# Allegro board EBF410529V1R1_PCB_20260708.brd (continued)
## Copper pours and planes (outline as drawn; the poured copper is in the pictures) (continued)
VCCA1V8_PLDO2_S0 on ART03: 19.24,54.5 19.46,54.71 32.26,54.71 36.53,58.98 36.53,62.76 36.75,62.99 41.5,62.99 41.73,62.76 41.73,61.85 41.48,61.59 38.86,61.59 38.43,61.16 38.43,58.37 33.76,53.7 19.46,53.7 19.24,53.91
VDD_3V3 on TOP: 57.86,13.82 57.86,12.67 57.96,12.57 59.18,12.57 59.69,13.08 59.69,13.79 59.51,13.97 58.01,13.97
VDD_3V3 on TOP: 129.6,60.21 129.81,60.01 129.81,58.97 129.59,58.75 128.57,58.75 128.32,59 128.32,60.03 128.5,60.21
VDD_3V3 on TOP: 6.17,72.67 4.52,72.67 4.37,72.82 4.37,73.76 4.14,73.99 2.97,73.99 2.97,74.4 3.4,74.4 3.63,74.63 3.63,76.25 5.38,76.25 5.38,75.23 5.21,75.06 4.93,75.06 4.78,74.9 4.78,73.23 4.93,73.08 6.17,73.08
VDD_3V3 on TOP: 9.55,41.27 9.42,41.4 8.76,41.4 8.64,41.53 8.64,43.66 9.25,43.66 9.25,42.52 9.58,42.19 11.07,42.19 11.61,41.66 11.61,40.54 11.73,40.41 12.75,40.41 12.88,40.54 12.88,41.81 13.11,42.04 14.91,42.04 15.09,41.86 15.09,39.85 14.83,39.6 9.7,39.6 9.55,39.75
VDD_3V3 on BOTTOM: 50.7,71.37 50.7,70.33 50.95,70.08 50.95,69.47 51.03,69.39 52.53,69.39 52.6,69.47 52.6,71.81 52.48,71.93 51,71.93 50.95,71.88 50.95,71.48 50.9,71.42 50.75,71.42
VDD_3V3 on BOTTOM: 122.94,15.26 124.26,15.26 124.49,15.03 125.7,15.03 125.86,15.18 125.86,16.32 125.7,16.48 124.56,16.48 124.43,16.35 124.43,16.07 124.26,15.89 122.94,15.89
VDD_3V3 on BOTTOM: 49.68,73.18 49.68,74.42 49.89,74.63 50.95,74.63 51.05,74.52 51.05,74.32 50.93,74.19 50.6,74.19 50.5,74.09 50.5,73.18
VDD_3V3 on ART03: 108.48,33.22 113.36,33.22 113.64,33.5 113.64,38.46 114.05,38.86 115.57,38.86 116.36,38.07 117.17,38.07 117.37,38.28 117.37,39.45 117.04,39.78 112.57,39.78 111.89,39.09 111.89,35.13 111.3,34.54 108.53,34.54 108.28,34.29 108.28,33.43
VDD_3V3 on ART03: 141.33,13.97 141.73,13.56 141.73,4.32 141.26,3.85 135.39,3.85 135.05,4.19 135.05,8.18 135.23,8.36 139.78,8.36 140.26,8.84 140.26,11.48 140.06,11.68 124.76,11.68 124.13,12.32 124.13,16.36 124.31,16.54 127.05,16.54 127.3,16.28 127.3,14.17 127.51,13.97
VDD_3V3 on PWR04: outline of 109 points within 3.81,12.52 139.24,85.72
VDD_5V on TOP: 64.35,12.65 65.18,13.48 65.18,14.2 64.95,14.43 63.73,14.43 63.3,14 63.3,12.88 63.53,12.65
VDD_5V on TOP: 11.23,31.85 8.59,31.85 8.48,31.75 8.48,30.78 8.59,30.68 11.23,30.68 11.33,30.78 11.33,31.75
VDD_5V on TOP: 82.52,68.66 82.52,66.85 82.73,66.65 84.45,66.65 84.61,66.8 84.61,68.45 84.4,68.66
VDD_5V on TOP: 8.59,12.62 11.71,12.62 11.94,12.4 11.94,11.43 11.76,11.25 8.74,11.25 8.59,11.4
VDD_5V on TOP: 9.6,48.84 10.62,48.84 10.77,49 10.77,50.09 10.39,50.47 10.39,51.38 10.29,51.49 9.6,51.49
VDD_5V on TOP: 41.88,72.72 41.88,73.69 41.97,73.77 41.97,74.05 41.88,74.14 40.87,74.14 40.77,74.04 40.77,72.9 40.94,72.72
VDD_5V on BOTTOM: 84.68,65.38 84.84,65.53 84.84,67.67 84.63,67.87 83.54,67.87 83.36,67.69 83.36,65.56 83.54,65.38
VDD_5V on BOTTOM: 9.35,23.83 11.73,23.83 11.91,24 11.91,24.82 11.73,24.99 9.55,24.99 9.32,24.77 9.32,23.85
VDD_5V on BOTTOM: 31.98,78.31 31.98,77.06 32.13,76.91 33.71,76.91 34.57,77.77 35.23,77.77 35.23,78.36 36.45,79.58 39.22,79.58 39.45,79.81 39.45,80.49 39.27,80.67 36.07,80.67 35.23,79.83 33.93,79.83 33.63,79.53 33.63,78.71 33.38,78.46 32.13,78.46
VDD_5V on BOTTOM: 41.88,72.72 41.99,72.82 41.99,74.12 41.86,74.24 40.69,74.24 40.56,74.12 40.56,72.87 40.72,72.72
VDD_5V on BOTTOM: 9.32,41.66 9.32,41.07 9.75,41.07 10.46,40.36 10.46,32.46 10.24,32.23 8.97,32.23 8.7,31.97 8.7,30.84 8.85,30.68 12.22,30.68 12.45,30.91 12.45,41.17 11.96,41.66
VDD_5V on BOTTOM: 117.65,15.26 117.73,15.08 117.91,15 119.23,15 119.41,15.08 119.48,15.26 119.48,16.25 119.41,16.43 119.23,16.5 117.91,16.5 117.73,16.43 117.65,16.25
VDD_5V on BOTTOM: 115.32,85.5 117.96,85.5 118.11,85.65 118.11,86.82 118.01,86.92 116.81,86.92 116.64,86.74 116.64,86.46 116.51,86.33 115.39,86.33 115.32,86.26
VDD_5V on BOTTOM: 3.89,55.37 3.89,53.14 4.09,52.93 5.33,52.93 7.21,54.81 7.21,56.49 8.15,57.43 8.15,58.85 8.05,58.95 5.92,58.95 5.82,58.85 5.82,56.01 5.38,55.58 4.09,55.58
VDD_5V on ART03: 9.88,45.14 10.13,45.39 10.13,47.75 10.74,48.36 10.74,50.11 10.64,50.22 10.49,50.22 8.19,47.92 8.19,47 7.8,46.61 7.44,46.61 7.21,46.38 7.21,45.29 7.37,45.14
VDD_5V on ART03: 118.14,16.41 119.41,16.41 119.56,16.26 119.56,14.91 119.35,14.71 115.62,14.71 113.94,16.38 113.94,38.43 114.15,38.63 115.32,38.63 115.6,38.35 115.6,17.04 116.61,16.03 117.75,16.03
VDD_5V on PWR04: outline of 86 points within 1.32,1.47 148.62,88.37
(no net) on TOP: 69.47,23.57 69.47,24.31 68.99,24.79 68.33,24.79 68.05,25.07 68.05,26.77 67.84,26.97 67.84,27.69 67.92,27.76 68.78,27.76 68.88,27.66 68.88,27.3 69.09,27.1 69.09,26.37 69.44,26.01 71.22,26.01 71.5,25.73 71.5,23.57
DSI_VDD3V3 on TOP: 142.29,14.1 142.37,13.92 142.54,13.84 144.48,13.84 144.65,13.92 144.73,14.1 144.73,14.5 144.65,14.68 144.48,14.76 142.54,14.76 142.37,14.68 142.29,14.5
DSI_VDD5V on TOP: 142.29,12.03 142.37,11.85 142.54,11.78 144.48,11.78 144.65,11.85 144.73,12.03 144.73,13.43 144.65,13.61 144.48,13.68 142.54,13.68 142.37,13.61 142.29,13.43
DSI_VDD5V on BOTTOM: 142.27,13.16 142.27,12.65 142.39,12.52 144.53,12.52 144.73,12.73 144.73,13.1 144.58,13.25 142.35,13.25
HDMI_5V on TOP: 85.93,68.66 85.93,66.88 86.08,66.73 90.99,66.73 91.14,66.87 91.14,66.87 91.5,67.24 91.5,67.61 91.27,67.84 87.3,67.84 87.12,68.02 87.12,68.66
MINIPCIE_3V3 on TOP: 125.17,30.43 118.97,30.43 118.62,30.78 118.62,32.23 118.87,32.49 119.74,32.49 119.94,32.69 119.94,34.39 120.03,34.48 123.52,34.48 123.77,34.23 123.77,33.05 125.17,31.65
MINIPCIE_3V3 on PWR04: 126.92,19.91 127.25,20.24 127.25,21.74 127.53,22.02 129.13,22.02 129.87,21.29 133.43,21.29 133.52,21.2 133.53,21.2 133.53,17.2 132.97,16.64 108.71,16.64 108.46,16.89 108.46,20.8 108.84,21.18 118.03,21.18 118.67,21.82 118.67,34.62 119,34.95 124,34.95 124.41,34.54 124.41,20.17 124.66,19.91
RMII0_VDD10 on TOP: 68,21.17 68,20.19 68.2,19.99 70.38,19.99 70.56,20.17 70.56,21.23 71.02,21.68 71.5,21.68 71.58,21.76 71.58,22.72 71.5,22.8 69.47,22.8 69.37,22.7 69.37,21.5 69.19,21.33 68.15,21.33
RMII0_VDD10 on PWR04: 63.02,27.61 69.75,27.61 70.05,27.3 70.05,20.17 69.88,19.99 68.22,19.99 68.15,20.07 68.15,25.88 67.74,26.29 63.04,26.29 62.74,26.59 62.74,27.33
RMII1_VDD10 on TOP: 84.23,21.16 84.23,20.17 84.4,19.99 86.64,19.99 86.79,20.14 86.79,21.21 87.25,21.67 87.73,21.67 87.81,21.74 87.81,22.71 87.73,22.78 85.7,22.78 85.6,22.68 85.6,21.49 85.42,21.31 84.38,21.31
TYPEC_CC1 on BOTTOM: 48.59,72.62 49.17,72.62 49.17,73.08 49.28,73.18 49.48,73.18 49.48,73.79 49.2,73.79 48.59,73.18
TYPEC_CC2 on BOTTOM: 50.7,73.79 51.33,73.79 51.59,73.53 51.59,72.62 51,72.62 51,73.03 50.85,73.18 50.7,73.18
USB_HUB_1V8 on PWR04: 98.15,42.47 98.15,38.3 98.48,37.97 112.67,37.97 112.83,38.13 112.83,39.07 112.67,39.22 99.82,39.22 99.49,39.55 99.49,42.37 99.19,42.67 98.35,42.67
N16958788 on BOTTOM: 9.07,72.11 10.87,72.11 11.13,72.36 11.13,81.13 10.85,81.41 9.09,81.41 8.81,81.13 8.81,72.36
N16959455 on BOTTOM: 5.21,65.63 6.71,65.63 7.16,65.18 7.16,62.81 7.52,62.46 8.13,62.46 8.2,62.38 8.2,61.11 8.13,61.04 5.84,61.04 5.77,61.11 5.77,62.41 6.35,62.99 6.35,64.8 6.22,64.92 5.21,64.92 5.16,64.97 5.16,65.58
N16961161 on BOTTOM: 12.57,65.63 13.94,65.63 14.53,65.05 14.53,62.81 14.88,62.46 15.49,62.46 15.57,62.38 15.57,61.11 15.49,61.04 13.21,61.04 13.13,61.11 13.13,62.41 13.72,62.99 13.72,64.8 13.59,64.92 12.57,64.92 12.45,65.05 12.45,65.51
N16971189 on TOP (solid shape): 68.88,27.66 68.88,27.3 69.09,27.1 69.09,26.37 69.44,26.01 70.97,26.01 71.5,25.47 71.5,23.57 69.47,23.57 69.47,24.31 68.99,24.79 68.33,24.79 68.05,25.07 68.05,26.77 67.84,26.97 67.84,27.69 67.92,27.76 68.78,27.76
N16976649 on TOP: 85.7,23.57 85.7,24.31 85.22,24.79 84.56,24.79 84.28,25.07 84.28,26.77 84.07,26.97 84.07,27.69 84.15,27.76 85.01,27.76 87.73,25.04 87.73,23.57
N17018699 on TOP: 5.92,32.72 5.82,32.61 5.82,31.5 5.92,31.39 7.59,31.39 8.46,32.26 9.19,32.26 9.19,33.22 9.04,33.38 8,33.38 7.34,32.72
N17022868 on BOTTOM: 5.92,22.68 9.8,22.68 9.93,22.81 9.93,23.44 9.88,23.5 8.31,23.5 7.8,24 5.92,24
N17023671 on TOP: 5.92,51.54 5.84,51.46 5.84,50.29 5.92,50.22 7.57,50.22 8,50.65 9.07,50.65 9.21,50.79 9.21,51.52 9.19,51.54
N17024139 on BOTTOM: 5.92,43.21 5.89,43.18 5.89,41.94 5.92,41.91 9.86,41.91 9.93,41.99 9.93,43.03 9.75,43.21
N17026345 on TOP: 9.19,13.61 5.99,13.61 5.89,13.51 5.89,12.19 5.99,12.09 7.7,12.09 8.61,13 9.19,13 9.25,13.06 9.25,13.56
N17043477 on TOP: 113.56,30.61 113.56,28.98 114.1,28.45 116.66,28.45 117.91,27.2 120.9,27.2 121.03,27.33 121.03,28.5 120.9,28.63 117.75,28.63 116.89,29.49 114.43,29.49 114.27,29.64 114.27,30.61
N17063858 on BOTTOM: 27.1,61.29 27.71,61.9 27.71,62.03 27.56,62.18 27.56,63.3 27.64,63.37 32.16,63.37 32.23,63.3 32.23,62.71 32.16,62.64 28.24,62.64 28.12,62.51 28.12,61.39 27.56,60.83 27.46,60.83 27.1,61.19
N17063899 on BOTTOM: 23.77,56.06 25.78,58.06 25.86,58.06 26.24,57.68 26.24,57.58 24.1,55.45 22.81,55.45 22.73,55.52 22.73,55.98 22.81,56.06
N17241015 on TOP: 74.55,12.34 73.33,12.34 73.25,12.42 71.98,12.42 71.98,11.53 72.11,11.4 74.55,11.4
N17241092 on TOP: 74.55,15.77 73.08,15.77 72.85,15.54 72.26,15.54 71.98,15.27 71.98,13.23 72.8,13.23 72.8,14.66 72.97,14.83 74.55,14.83
N17313600 on TOP: 36.04,67.31 37.24,67.31 37.34,67.41 37.34,69.7 37.49,69.85 40.92,69.85 41.07,69.7 41.78,69.7 41.88,69.8 41.88,71.91 41.81,71.98 41.15,71.98 41.07,71.91 41.07,71.22 40.92,71.07 36.14,71.07 36.02,70.94 36.02,69.88 35.81,69.67 33.68,69.67 33.32,70.03 30.76,70.03 30.12,69.39 27.66,69.39 27.53,69.27 27.53,68.88 27.66,68.76 30.43,68.76 30.84,69.16 33.22,69.16 33.74,68.65 33.74,68.1 35.74,68.1 35.92,67.92 35.92,67.44
N17315365 on BOTTOM: 36.04,67.31 37.13,67.31 37.24,67.41 37.24,69.6 37.49,69.85 40.92,69.85 41.07,69.7 41.81,69.7 41.88,69.77 41.88,71.91 41.78,72.01 41.17,72.01 41.07,71.91 41.07,71.22 40.92,71.07 36.14,71.07 36.02,70.94 36.02,69.88 35.81,69.67 33.68,69.67 33.32,70.03 30.84,70.03 30.43,70.43 27.71,70.43 27.56,70.28 27.56,69.93 27.71,69.77 30.07,69.77 30.68,69.16 33.22,69.16 33.63,68.76 33.63,68.11 33.64,68.1 35.74,68.1 35.92,67.92 35.92,67.44

Small or netless copper shapes (teardrops, artwork), in the pictures only: 42 on TOP, 64 on BOTTOM, 6 on ART03

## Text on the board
Ref Des/Silkscreen Bottom: D | D:USB3.0 | 20260708 | EBF410529V1R1 | CAM4 | CAM2 | U10RX | U10TX | T10RX | T10TX | R2OUT | T2IN | U8RX | U8TX | T8RX | T8TX | R1OUT | T1IN | YYWW
Ref Des/Silkscreen Top: GND | RTC | RX | TX | A | 1L | 1H | CAN | 0L | 0H | 2A | 2B | RS485 | EBF410529V1R1 | 1A | 20260708 | 1B | T1OUT | JLCJLCJLCJLCJLCJLC | C | EarPhone | R1IN | RS232 | T2OUT | ETH0 | R2IN | 3V3 | POWER | OUTPUT | 5V | 12V | ETH1 | IN7 | IN6 | SARADC | IN5 | B | IN3 | 1V8 | FAN | UART10 | NC | UART8 | U:USB2.0 | USB2.0 HOST | IR | CAM3 | CAM1 | CAM0 | SPK_L | SPK_R | PWR | MIPI DSI | ON/OFF | MASKROM | RECOVERY | SYS | DCIN:12V
COMPVAL_TYPE_TOP: C268 | C1 | C267 | C9 | SS2 | C59 | C61 | R18 | C25 | C19 | C36 | L8 | R20 | L7 | C5 | C12 | C26 | C20 | C29 | C23 | L4 | C79 | L9 | C27 | C86 | C87 | L6 | C75 | C73 | R15 | C47 | L5 | L11 | R16 | C49 | C83 | R23 | C90 | R26 | R25 | C89 | C43 | Q1 | C135 | R100 | C246 | C245 | R102 | R101 | R68 | R73 | R74 | R66 | R71 | R72 | R69 | Q2 | R98 | R99 | R97 | R96 | R55 | R58 | R62 | R59 | R76 | Q4 | Q3 | R64 | R63 | R60 | C192 | C193 | C196 | C194 | C252 | R109 | R53 | C203 | R54 | Y2 | C202 | R52 | R51 | R108 | R29 | C128 | SS1 | R79 | R82 | R75 | R77 | R78 | R81 | R86 | R80 | C2 | C10 | C3 | R4 | C34 | C63 | R1 | C11 | R3 | R6 | U1 | U2 | C62 | C57 | C33 | C64 | R2 | R5 | C8 | C16 | C7 | C15 | C65 | C58 | C32 | C190 | C70 | L1 | L2 | C31 | R17 | C72 | C60 | C30 | R12 | C71 | L3 | C54 | U3 | U6 | C52 | C42 | L12 | C41 | C37 | R19 | R24 | C84 | R21 | C46 | R14 | L10 | C74 | C48 | U7 | C50 | C44 | C81 | C51 | C45 | C82 | C80 | D1 | R7 | C137 | C176 | C177 | C183 | C184 | R8 | R9 | C185 | R43 | R45 | R44 | C182 | R47 | R46 | R42 | R110 | R87 | R48 | C157 | C161 | C201 | U4 | U5 | R30 | C129 | Y1 | C269 | 2
User.13: FIGURE | FINISHED_SIZE | 8.0 | 12.0 | 19.689 | 21.65 | 25.591 | 27.559 | 39.37 | 47.24 | 72.051 | 78.74 | 94.5 | 118.11 | 166.142 | 35.429 | 43.311 | 62.988 | 78.701 | 125.98 | 127.949 | 47.24x19.689 | 59.059x29.531 | 62.988x23.618 | 66.929x19.689 | 70.902x15.701 | 74.799x23.618 | 106.299x35.429 | DRILL CHART: TOP to BOTTOM | ALL UNITS ARE IN MILS | ROTATION | - | 0.000 | 90.000 | PLATED | NON-PLATED | QTY | 2027 | 53 | 2 | 19 | 18 | 26 | 9 | 8 | 22 | 4 | 3 | 7
